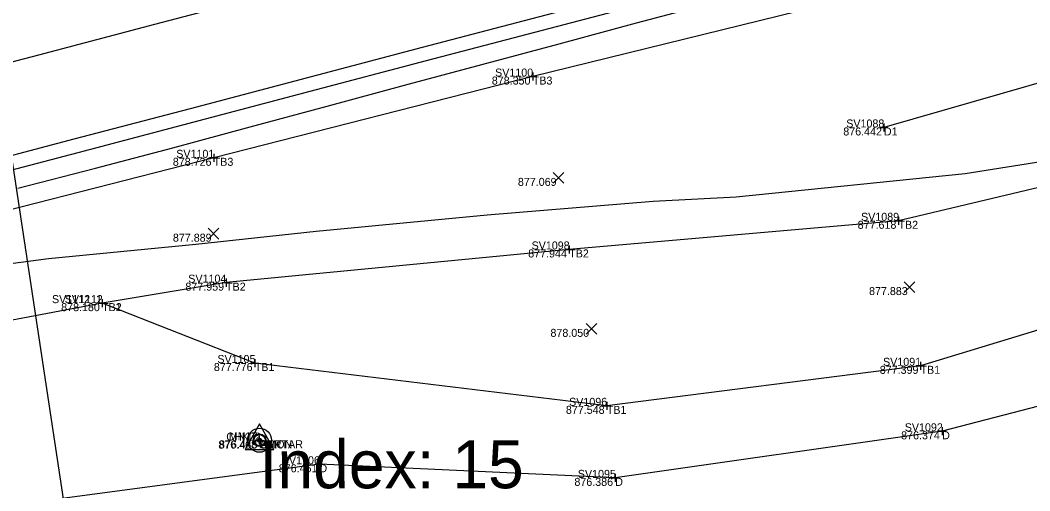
# Model space of a CAD drawing. Extents: x 2125299 to 2129212, y 713100 to 714300.
# Drawn here: x 2128168.4 to 2128294.5, y 713987.2 to 714046 of the extents above; entities that cross this region are included whole.
import ezdxf

# ---------------------------------------------------------------- set-up
doc = ezdxf.new("R2010")
doc.units = 0
for name, color, linetype in [('_CIVIL_CONSTRUCTION', 7, 'Continuous'), ('DR_X_Ditch', 7, 'Continuous'), ('PV_X_EOP', 7, 'Continuous'), ('PV_X_Shoulder_Rumble_Strip', 7, 'Continuous'), ('RS_Raster1', 7, 'Continuous'), ('RW_P_Esmt_TMP', 7, 'Continuous'), ('RW_X_CL', 7, 'Continuous'), ('RW_X_Esmt_CH', 7, 'Continuous'), ('RW_X_Fee_WL', 7, 'Continuous'), ('SC_Scratch2', 7, 'Continuous'), ('SV_P_Aerial_Targets', 7, 'Continuous'), ('SV_X_Mon_Cells_Found', 7, 'Continuous'), ('SV_X_Text_Elevation', 7, 'Continuous'), ('SV_X_Top_of_Bank', 7, 'Continuous'), ('UT_X_Overhead_Telecom_FO', 7, 'Continuous')]:
    doc.layers.add(name, color=color, linetype=linetype)

msp = doc.modelspace()

# ---------------------------------------------------------------- linework, layer by layer
at = {"layer": '_CIVIL_CONSTRUCTION'}
msp.add_line((2128198.3, 713993.56), (2128198.3, 713993.56), dxfattribs=at)
msp.add_lwpolyline([(2128156.2, 714037.91), (2128170.7, 714041.73), (2128185.21, 714045.56), (2128199.71, 714049.38), (2128214.22, 714053.21), (2128228.72, 714057.03), (2128243.22, 714060.86), (2128257.73, 714064.68), (2128272.23, 714068.51), (2128286.73, 714072.34), (2128301.23, 714076.18), (2128315.73, 714080.03), (2128330.23, 714083.87), (2128344.73, 714087.71), (2128359.23, 714091.55), (2128373.73, 714095.39), (2128388.23, 714099.23), (2128402.73, 714103.07), (2128417.23, 714106.91)], dxfattribs=at)
msp.add_circle((2128198.3, 713993.56), 0.25, dxfattribs=at)
at = {"layer": 'DR_X_Ditch'}
for points in [[(2128525.29, 714099.16), (2128497.16, 714092.88), (2128436.33, 714076.51), (2128391.32, 714063.78), (2128330.37, 714048.18), (2128276.31, 714032.64)], [(2128539.96, 714065.48), (2128533.93, 714063.76), (2128504.91, 714054.76), (2128447.02, 714038.39), (2128399.37, 714025.09), (2128341.85, 714009.81), (2128283.59, 713994.68), (2128242.74, 713988.86), (2128205.78, 713990.56), (2128171.48, 713986), (2128143.07, 713980.05), (2128117.8, 713975.62)]]:
    msp.add_lwpolyline(points, dxfattribs=at)
at = {"layer": 'PV_X_EOP'}
msp.add_lwpolyline([(2128168.1, 714025.06), (2128177.78, 714027.55), (2128187.45, 714030.11), (2128197.11, 714032.71), (2128206.76, 714035.31), (2128216.42, 714037.91), (2128226.07, 714040.51), (2128235.73, 714043.11), (2128245.39, 714045.7), (2128255.06, 714048.26), (2128264.72, 714050.82), (2128274.39, 714053.38), (2128284.06, 714055.94), (2128293.72, 714058.5), (2128303.39, 714061.06)], dxfattribs=at)
at = {"layer": 'PV_X_Shoulder_Rumble_Strip'}
msp.add_lwpolyline([(2128092.76, 714007.7), (2128103.1, 714010.43), (2128117.61, 714014.25), (2128132.11, 714018.07), (2128146.62, 714021.89), (2128161.12, 714025.71), (2128175.62, 714029.53), (2128190.13, 714033.35), (2128204.63, 714037.17), (2128219.14, 714040.99), (2128233.64, 714044.81), (2128248.15, 714048.63), (2128262.65, 714052.45), (2128277.16, 714056.28), (2128291.66, 714060.12), (2128306.16, 714063.95), (2128320.66, 714067.79), (2128335.16, 714071.62), (2128349.66, 714075.46), (2128364.16, 714079.29), (2128378.66, 714083.13), (2128393.16, 714086.96), (2128407.66, 714090.8), (2128422.17, 714094.63)], dxfattribs=at)
at = {"layer": 'RS_Raster1'}
msp.add_lwpolyline([(2128363.11, 714044.81), (2128334.85, 714036.86), (2128313.75, 714031.74), (2128301.97, 714029.31), (2128286.46, 714026.84), (2128257.87, 714023.95), (2128247.5, 714023.4), (2128226.75, 714021.68), (2128205.39, 714019.64), (2128190.35, 714018), (2128171.93, 714016.23), (2128154.59, 714013.93), (2128141.53, 714011.83), (2128129.8, 714009.97), (2128117.74, 714007.84), (2128109.17, 714006.09), (2128099.58, 714004.27), (2128089.89, 714001.93)], dxfattribs=at)
at = {"layer": 'RW_X_CL'}
for radius in [1.5, 0.8]:
    msp.add_circle((2128198.3, 713993.56), radius, dxfattribs=at)
at = {"layer": 'SC_Scratch2'}
msp.add_lwpolyline([(2128160.65, 714027.38), (2128175.15, 714031.2), (2128189.66, 714035.02), (2128204.16, 714038.84), (2128218.67, 714042.66), (2128233.17, 714046.48), (2128247.68, 714050.3), (2128262.18, 714054.12), (2128276.69, 714057.95), (2128291.19, 714061.78), (2128305.69, 714065.62), (2128320.19, 714069.46), (2128334.69, 714073.29), (2128349.19, 714077.13), (2128363.69, 714080.96), (2128378.2, 714084.8), (2128392.7, 714088.63), (2128407.2, 714092.47), (2128421.7, 714096.3)], dxfattribs=at)
at = {"layer": 'SV_P_Aerial_Targets'}
msp.add_line((2128198.3, 713993.56), (2128198.3, 713993.56), dxfattribs=at)
msp.add_lwpolyline([(2128196.5, 713992.4), (2128200.1, 713992.4), (2128198.3, 713995.62)], close=True, dxfattribs=at)
for radius in [0.7, 0.16]:
    msp.add_circle((2128198.3, 713993.56), radius, dxfattribs=at)
at = {"layer": 'SV_X_Mon_Cells_Found'}
for p, q in [((2128231.94, 714039), (2128232.94, 714039)), ((2128232.44, 714039.5), (2128232.44, 714038.5)), ((2128232.44, 714039), (2128232.44, 714039)), ((2128275.81, 714032.64), (2128276.81, 714032.64)), ((2128276.31, 714033.14), (2128276.31, 714032.14)), ((2128276.31, 714032.64), (2128276.31, 714032.64)), ((2128192.07, 714028.85), (2128193.07, 714028.85)), ((2128192.57, 714029.35), (2128192.57, 714028.35)), ((2128192.57, 714028.85), (2128192.57, 714028.85)), ((2128277.64, 714020.98), (2128278.64, 714020.98)), ((2128278.14, 714021.48), (2128278.14, 714020.48)), ((2128278.14, 714020.98), (2128278.14, 714020.98)), ((2128236.49, 714017.4), (2128237.49, 714017.4)), ((2128236.99, 714017.9), (2128236.99, 714016.9)), ((2128236.99, 714017.4), (2128236.99, 714017.4)), ((2128193.61, 714013.25), (2128194.61, 714013.25)), ((2128194.11, 714013.75), (2128194.11, 714012.75)), ((2128194.11, 714013.25), (2128194.11, 714013.25)), ((2128178.12, 714010.69), (2128179.12, 714010.69)), ((2128178.12, 714010.69), (2128179.12, 714010.69)), ((2128178.62, 714011.19), (2128178.62, 714010.19)), ((2128178.62, 714011.19), (2128178.62, 714010.19)), ((2128178.62, 714010.69), (2128178.62, 714010.69)), ((2128178.62, 714010.69), (2128178.62, 714010.69)), ((2128197.2, 714003.21), (2128198.2, 714003.21)), ((2128197.7, 714003.71), (2128197.7, 714002.71)), ((2128197.7, 714003.21), (2128197.7, 714003.21)), ((2128280.89, 714003.36), (2128280.89, 714002.36)), ((2128280.39, 714002.86), (2128281.39, 714002.86)), ((2128280.89, 714002.86), (2128280.89, 714002.86)), ((2128241.69, 713998.36), (2128241.69, 713997.36)), ((2128241.19, 713997.86), (2128242.19, 713997.86)), ((2128241.69, 713997.86), (2128241.69, 713997.86)), ((2128283.09, 713994.68), (2128284.09, 713994.68)), ((2128283.59, 713995.18), (2128283.59, 713994.18)), ((2128283.59, 713994.68), (2128283.59, 713994.68)), ((2128197.75, 713993.51), (2128198.75, 713993.51)), ((2128198.25, 713994.01), (2128198.25, 713993.01)), ((2128198.25, 713993.51), (2128198.25, 713993.51)), ((2128205.28, 713990.56), (2128206.28, 713990.56)), ((2128205.78, 713991.06), (2128205.78, 713990.06)), ((2128205.78, 713990.56), (2128205.78, 713990.56)), ((2128242.74, 713989.36), (2128242.74, 713988.36)), ((2128242.24, 713988.86), (2128243.24, 713988.86)), ((2128242.74, 713988.86), (2128242.74, 713988.86))]:
    msp.add_line(p, q, dxfattribs=at)
at = {"layer": 'SV_X_Text_Elevation'}
for p, q in [((2128235, 714025.68), (2128236.33, 714027.01)), ((2128235, 714027.01), (2128236.33, 714025.68)), ((2128191.89, 714018.7), (2128193.22, 714020.04)), ((2128191.89, 714020.04), (2128193.22, 714018.7)), ((2128278.85, 714012.03), (2128280.19, 714013.37)), ((2128278.85, 714013.37), (2128280.19, 714012.03)), ((2128239.1, 714006.82), (2128240.43, 714008.15)), ((2128239.1, 714008.15), (2128240.43, 714006.82))]:
    msp.add_line(p, q, dxfattribs=at)
at = {"layer": 'SV_X_Top_of_Bank'}
for points in [[(2128621.75, 714139.89), (2128575.4, 714127.43), (2128536.54, 714118.82), (2128494.56, 714106.73), (2128494.59, 714106.74), (2128431.42, 714092.25), (2128387.26, 714080.92), (2128325.7, 714062.91), (2128270.25, 714048.29), (2128232.44, 714039), (2128192.57, 714028.85), (2128120.54, 714010.42)], [(2128630.23, 714112.45), (2128582.67, 714099.87), (2128543.67, 714088.86), (2128499.9, 714077.56), (2128440.42, 714062.73), (2128393.57, 714052.94), (2128334.24, 714034.3), (2128278.14, 714020.98), (2128236.99, 714017.4), (2128194.11, 714013.25), (2128178.62, 714010.69), (2128139.13, 714003.23), (2128093.27, 713996.96)], [(2128632.64, 714103.31), (2128584.74, 714089.99), (2128545.97, 714080.06), (2128501.31, 714068.27), (2128443.11, 714052.88), (2128397.55, 714033.79), (2128338.65, 714020.42), (2128280.89, 714002.86), (2128241.69, 713997.86), (2128197.7, 714003.21), (2128178.62, 714010.69)]]:
    msp.add_lwpolyline(points, dxfattribs=at)
at = {"layer": 'UT_X_Overhead_Telecom_FO'}
msp.add_lwpolyline([(2128144.62, 714178.88), (2128199.4, 713816.51)], dxfattribs=at)

# ---------------------------------------------------------------- texts
at = {"layer": '_CIVIL_CONSTRUCTION'}
msp.add_text('Index: 15', height=6, dxfattribs=at).set_placement((2128198.3, 713987.56))
at = {"layer": 'RW_P_Esmt_TMP'}
for s, p in [('TB3', (2128232.44, 714038)), ('D1', (2128276.31, 714031.64)), ('TB3', (2128192.57, 714027.85)), ('TB2', (2128278.14, 714019.98)), ('TB2', (2128236.99, 714016.4)), ('TB2', (2128194.11, 714012.25)), ('TB2', (2128178.62, 714009.69)), ('TB1', (2128178.62, 714009.69)), ('TB1', (2128197.7, 714002.21)), ('TB1', (2128280.89, 714001.86)), ('TB1', (2128241.69, 713996.86)), ('D', (2128283.59, 713993.68)), ('AERTAR', (2128198.3, 713992.56)), ('CHK', (2128198.25, 713992.51)), ('CMON', (2128198.3, 713992.56)), ('D', (2128205.78, 713989.56)), ('D', (2128242.74, 713987.86))]:
    msp.add_text(s, height=1, dxfattribs=at).set_placement(p)
at = {"layer": 'RW_X_Esmt_CH'}
for s, p in [('SV1100', (2128227.73, 714039)), ('SV1088', (2128271.61, 714032.64)), ('SV1101', (2128187.89, 714028.85)), ('SV1089', (2128273.46, 714020.98)), ('SV1098', (2128232.29, 714017.4)), ('SV1104', (2128189.39, 714013.25)), ('SV1112_1', (2128172.36, 714010.69)), ('SV1112', (2128173.95, 714010.69)), ('SV1105', (2128193.03, 714003.21)), ('SV1091', (2128276.21, 714002.86)), ('SV1096', (2128236.98, 713997.86)), ('SV1092', (2128278.92, 713994.68)), ('CHK02', (2128194.14, 713993.51)), ('MN17', (2128194.45, 713993.56)), ('MN17', (2128194.45, 713993.56)), ('SV1106', (2128201.08, 713990.56)), ('SV1095', (2128238.07, 713988.86))]:
    msp.add_text(s, height=1, dxfattribs=at).set_placement(p)
at = {"layer": 'RW_X_Fee_WL'}
for s, p in [('878.350', (2128227.32, 714038)), ('876.442', (2128271.24, 714031.64)), ('878.726', (2128187.46, 714027.85)), ('877.069', (2128230.58, 714025.34)), ('877.618', (2128273.04, 714019.98)), ('877.889', (2128187.47, 714018.37)), ('877.944', (2128231.87, 714016.4)), ('877.959', (2128189.03, 714012.25)), ('877.883', (2128274.46, 714011.7)), ('878.180', (2128173.51, 714009.69)), ('878.180', (2128173.51, 714009.69)), ('878.050', (2128234.65, 714006.48)), ('877.776', (2128192.59, 714002.21)), ('877.399', (2128275.8, 714001.86)), ('877.548', (2128236.58, 713996.86)), ('876.374', (2128278.47, 713993.68)), ('876.468', (2128193.15, 713992.51)), ('876.445', (2128193.23, 713992.56)), ('876.445', (2128193.23, 713992.56)), ('876.451', (2128200.7, 713989.56)), ('876.386', (2128237.64, 713987.86))]:
    msp.add_text(s, height=1, dxfattribs=at).set_placement(p)

doc.saveas('drawing.dxf')
